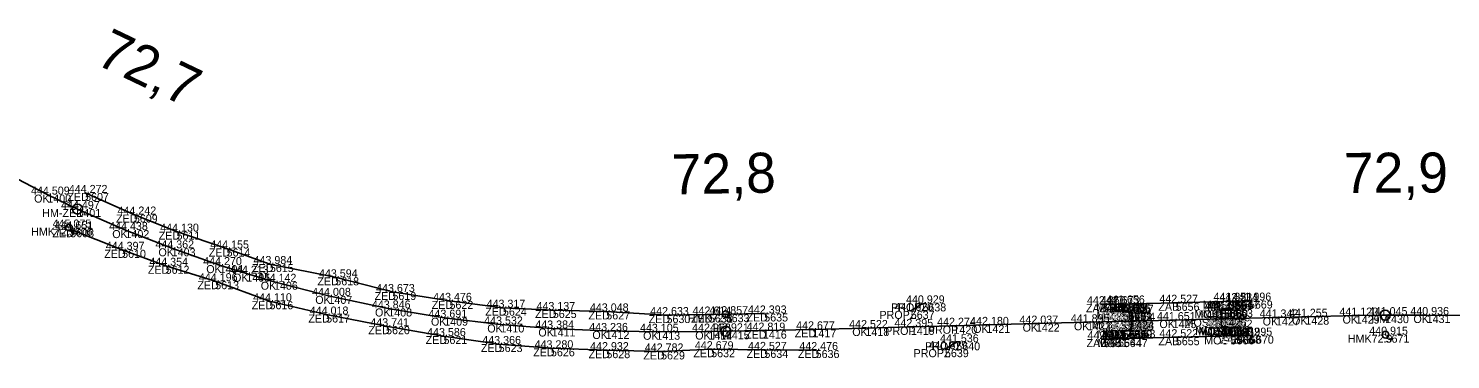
# Model space of a CAD drawing. Extents: x -621782 to -610392, y -1141853 to -1122321.
# Drawn here: x -620166.2 to -619952.9, y -1128869.1 to -1128819.5 of the extents above; entities that cross this region are included whole.
import ezdxf

# ---------------------------------------------------------------- set-up
doc = ezdxf.new("R2010")
doc.units = 0
for name, color, linetype in [('Vrstva 1', 7, 'Continuous'), ('Vrstva 13', 7, 'Continuous'), ('Vrstva 17', 7, 'Continuous'), ('Vrstva 18', 7, 'Continuous'), ('Vrstva 19', 7, 'Continuous'), ('Vrstva 60', 7, 'Continuous'), ('Vrstva 61', 7, 'Continuous'), ('Vrstva 62', 7, 'Continuous'), ('Vrstva 7', 7, 'Continuous')]:
    doc.layers.add(name, color=color, linetype=linetype)

msp = doc.modelspace()

# ---------------------------------------------------------------- linework, layer by layer
at = {"layer": 'Vrstva 1'}
msp.add_lwpolyline([(-620170.13, -1128840.86), (-620163.39, -1128844.36), (-620158.88, -1128846.52), (-620151.67, -1128849.68), (-620144.73, -1128852.41), (-620137.56, -1128854.93), (-620133.54, -1128856.21), (-620129.39, -1128857.43), (-620121.22, -1128859.54), (-620112.25, -1128861.43), (-620103.86, -1128862.81), (-620095.42, -1128863.83), (-620087.75, -1128864.43), (-620079.66, -1128864.8), (-620072.05, -1128864.92), (-620064.23, -1128864.89), (-620061.62, -1128864.85), (-620056.06, -1128864.75), (-620048.63, -1128864.56), (-620040.68, -1128864.36), (-620033.87, -1128864.19), (-620027.48, -1128864.02), (-620022.53, -1128863.89), (-620015.12, -1128863.7), (-620007.43, -1128863.5), (-620000.99, -1128863.33), (-619994.61, -1128863.17), (-619987.09, -1128862.97), (-619979.11, -1128862.78), (-619974.7, -1128862.67), (-619967.14, -1128862.5), (-619962.74, -1128862.43), (-619956.51, -1128862.41), (-619950.41, -1128862.49)], dxfattribs=at)
at = {"layer": 'Vrstva 13'}
for points in [[(-620157.72, -1128844.11), (-620150.41, -1128847.35), (-620144.01, -1128849.91), (-620136.5, -1128852.44), (-620130.01, -1128854.77), (-620120.2, -1128856.76), (-620111.63, -1128858.96), (-620103.07, -1128860.29), (-620095.05, -1128861.31), (-620087.57, -1128861.66), (-620079.55, -1128861.87), (-620070.52, -1128862.42), (-620064.16, -1128862.34), (-620055.86, -1128862.18)], [(-620048.15, -1128867.66), (-620055.84, -1128867.64), (-620063.82, -1128867.54), (-620071.33, -1128867.87), (-620079.54, -1128867.68), (-620087.85, -1128867.4), (-620095.69, -1128866.76), (-620103.97, -1128865.56), (-620112.58, -1128864.09), (-620121.57, -1128862.34), (-620130.07, -1128860.35), (-620138.21, -1128857.34), (-620145.64, -1128855.03), (-620152.17, -1128852.64), (-620159.95, -1128849.55)]]:
    msp.add_lwpolyline(points, dxfattribs=at)
at = {"layer": 'Vrstva 17'}
for points in [[(-619983.17, -1128860.25), (-619985.15, -1128860.33), (-619994.15, -1128860.57), (-620002.94, -1128860.77), (-620005.01, -1128860.79)], [(-620004.92, -1128866.03), (-620002.79, -1128865.97), (-619994.13, -1128865.74), (-619984.91, -1128865.52), (-619983.01, -1128865.5)]]:
    msp.add_lwpolyline(points, dxfattribs=at)
at = {"layer": 'Vrstva 18'}
for points in [[(-620001.93, -1128866.02), (-620001.95, -1128864.72), (-620001.24, -1128864.71), (-620001.23, -1128864.64), (-620000.76, -1128864.62), (-620000.8, -1128862.07), (-620001.26, -1128862.08), (-620001.29, -1128861.9), (-620002.09, -1128861.93), (-620002.14, -1128860.68)], [(-619985.93, -1128865.62), (-619985.98, -1128864.31), (-619986.77, -1128864.33), (-619986.79, -1128864.17), (-619987.28, -1128864.2), (-619987.39, -1128861.71), (-619986.9, -1128861.67), (-619986.9, -1128861.55), (-619986.14, -1128861.54), (-619986.12, -1128860.27)]]:
    msp.add_lwpolyline(points, dxfattribs=at)
at = {"layer": 'Vrstva 19'}
for p, q in [((-620033.88, -1128861.79), (-620032.14, -1128860.67)), ((-620028.76, -1128867.53), (-620027.05, -1128866.5))]:
    msp.add_line(p, q, dxfattribs=at)
at = {"layer": 'Vrstva 60'}
for p, q in [((-620163.39, -1128844.36), (-620163.39, -1128844.36)), ((-620157.72, -1128844.11), (-620157.72, -1128844.11)), ((-620158.88, -1128846.52), (-620158.88, -1128846.52)), ((-620150.41, -1128847.35), (-620150.41, -1128847.35)), ((-620160.15, -1128849.3), (-620160.15, -1128849.3)), ((-620159.95, -1128849.55), (-620159.95, -1128849.55)), ((-620151.67, -1128849.68), (-620151.67, -1128849.68)), ((-620144.01, -1128849.91), (-620144.01, -1128849.91)), ((-620152.17, -1128852.64), (-620152.17, -1128852.64)), ((-620144.73, -1128852.41), (-620144.73, -1128852.41)), ((-620136.5, -1128852.44), (-620136.5, -1128852.44)), ((-620145.64, -1128855.03), (-620145.64, -1128855.03)), ((-620137.56, -1128854.93), (-620137.56, -1128854.93)), ((-620130.01, -1128854.77), (-620130.01, -1128854.77)), ((-620138.21, -1128857.34), (-620138.21, -1128857.34)), ((-620133.54, -1128856.21), (-620133.54, -1128856.21)), ((-620129.39, -1128857.43), (-620129.39, -1128857.43)), ((-620120.2, -1128856.76), (-620120.2, -1128856.76)), ((-620121.22, -1128859.54), (-620121.22, -1128859.54)), ((-620111.63, -1128858.96), (-620111.63, -1128858.96)), ((-620130.07, -1128860.35), (-620130.07, -1128860.35)), ((-620112.25, -1128861.43), (-620112.25, -1128861.43)), ((-620103.07, -1128860.29), (-620103.07, -1128860.29)), ((-620095.05, -1128861.31), (-620095.05, -1128861.31)), ((-620087.57, -1128861.66), (-620087.57, -1128861.66)), ((-620079.55, -1128861.87), (-620079.55, -1128861.87)), ((-620061.64, -1128862.29), (-620061.64, -1128862.29)), ((-620055.86, -1128862.18), (-620055.86, -1128862.18)), ((-620033.88, -1128861.79), (-620033.88, -1128861.79)), ((-620032.14, -1128860.67), (-620032.14, -1128860.67)), ((-620005.01, -1128860.79), (-620005.01, -1128860.79)), ((-620002.94, -1128860.77), (-620002.94, -1128860.77)), ((-620002.14, -1128860.68), (-620002.14, -1128860.68)), ((-620002.09, -1128861.93), (-620002.09, -1128861.93)), ((-620001.29, -1128861.9), (-620001.29, -1128861.9)), ((-620001.26, -1128862.08), (-620001.26, -1128862.08)), ((-620000.8, -1128862.07), (-620000.8, -1128862.07)), ((-619994.15, -1128860.57), (-619994.15, -1128860.57)), ((-619987.39, -1128861.71), (-619987.39, -1128861.71)), ((-619986.9, -1128861.55), (-619986.9, -1128861.55)), ((-619986.9, -1128861.67), (-619986.9, -1128861.67)), ((-619986.14, -1128861.54), (-619986.14, -1128861.54)), ((-619986.12, -1128860.27), (-619986.12, -1128860.27)), ((-619985.15, -1128860.33), (-619985.15, -1128860.33)), ((-619983.17, -1128860.25), (-619983.17, -1128860.25)), ((-620121.57, -1128862.34), (-620121.57, -1128862.34)), ((-620112.58, -1128864.09), (-620112.58, -1128864.09)), ((-620103.86, -1128862.81), (-620103.86, -1128862.81)), ((-620095.42, -1128863.83), (-620095.42, -1128863.83)), ((-620087.75, -1128864.43), (-620087.75, -1128864.43)), ((-620070.52, -1128862.42), (-620070.52, -1128862.42)), ((-620064.16, -1128862.34), (-620064.16, -1128862.34)), ((-620040.68, -1128864.36), (-620040.68, -1128864.36)), ((-620033.87, -1128864.19), (-620033.87, -1128864.19)), ((-620027.48, -1128864.02), (-620027.48, -1128864.02)), ((-620022.53, -1128863.89), (-620022.53, -1128863.89)), ((-620015.12, -1128863.7), (-620015.12, -1128863.7)), ((-620007.43, -1128863.5), (-620007.43, -1128863.5)), ((-620000.99, -1128863.33), (-620000.99, -1128863.33)), ((-619994.61, -1128863.17), (-619994.61, -1128863.17)), ((-619987.28, -1128864.2), (-619987.28, -1128864.2)), ((-619987.09, -1128862.97), (-619987.09, -1128862.97)), ((-619986.79, -1128864.17), (-619986.79, -1128864.17)), ((-619986.77, -1128864.33), (-619986.77, -1128864.33)), ((-619985.98, -1128864.31), (-619985.98, -1128864.31)), ((-619979.11, -1128862.78), (-619979.11, -1128862.78)), ((-619974.7, -1128862.67), (-619974.7, -1128862.67)), ((-619967.14, -1128862.5), (-619967.14, -1128862.5)), ((-619962.74, -1128862.43), (-619962.74, -1128862.43)), ((-619956.51, -1128862.41), (-619956.51, -1128862.41)), ((-620103.97, -1128865.56), (-620103.97, -1128865.56)), ((-620079.66, -1128864.8), (-620079.66, -1128864.8)), ((-620072.05, -1128864.92), (-620072.05, -1128864.92)), ((-620064.23, -1128864.89), (-620064.23, -1128864.89)), ((-620061.62, -1128864.85), (-620061.62, -1128864.85)), ((-620056.06, -1128864.75), (-620056.06, -1128864.75)), ((-620048.63, -1128864.56), (-620048.63, -1128864.56)), ((-620027.05, -1128866.5), (-620027.05, -1128866.5)), ((-620004.92, -1128866.03), (-620004.92, -1128866.03)), ((-620002.79, -1128865.97), (-620002.79, -1128865.97)), ((-620001.95, -1128864.72), (-620001.95, -1128864.72)), ((-620001.93, -1128866.02), (-620001.93, -1128866.02)), ((-620001.24, -1128864.71), (-620001.24, -1128864.71)), ((-620001.23, -1128864.64), (-620001.23, -1128864.64)), ((-620000.76, -1128864.62), (-620000.76, -1128864.62)), ((-619994.13, -1128865.74), (-619994.13, -1128865.74)), ((-619985.93, -1128865.62), (-619985.93, -1128865.62)), ((-619984.91, -1128865.52), (-619984.91, -1128865.52)), ((-619983.01, -1128865.5), (-619983.01, -1128865.5)), ((-619962.67, -1128865.36), (-619962.67, -1128865.36)), ((-620095.69, -1128866.76), (-620095.69, -1128866.76)), ((-620087.85, -1128867.4), (-620087.85, -1128867.4)), ((-620079.54, -1128867.68), (-620079.54, -1128867.68)), ((-620071.33, -1128867.87), (-620071.33, -1128867.87)), ((-620063.82, -1128867.54), (-620063.82, -1128867.54)), ((-620055.84, -1128867.64), (-620055.84, -1128867.64)), ((-620048.15, -1128867.66), (-620048.15, -1128867.66)), ((-620028.76, -1128867.53), (-620028.76, -1128867.53))]:
    msp.add_line(p, q, dxfattribs=at)
at = {"layer": 'Vrstva 7'}
for p, q in [((-620160.19, -1128849.28), (-620160.1, -1128849.32)), ((-620061.69, -1128862.29), (-620061.59, -1128862.29)), ((-619962.72, -1128865.36), (-619962.62, -1128865.36))]:
    msp.add_line(p, q, dxfattribs=at)
for centre, radius in [((-620158.88, -1128846.52), 0.75), ((-620160.15, -1128849.3), 0.5), ((-620061.64, -1128862.29), 0.5), ((-619962.74, -1128862.43), 0.75), ((-620061.62, -1128864.85), 0.75), ((-619962.67, -1128865.36), 0.5)]:
    msp.add_circle(centre, radius, dxfattribs=at)

# ---------------------------------------------------------------- texts
at = {"layer": 'Vrstva 60'}
for s, p in [('1400', (-620163.39, -1128845.56)), ('5607', (-620157.72, -1128845.31)), ('1401', (-620158.88, -1128847.72)), ('5609', (-620150.41, -1128848.55)), ('5606', (-620160.15, -1128850.5)), ('5608', (-620159.95, -1128850.75)), ('1402', (-620151.67, -1128850.88)), ('5611', (-620144.01, -1128851.11)), ('5610', (-620152.17, -1128853.84)), ('1403', (-620144.73, -1128853.61)), ('5614', (-620136.5, -1128853.64)), ('5612', (-620145.64, -1128856.23)), ('1404', (-620137.56, -1128856.13)), ('5615', (-620130.01, -1128855.97)), ('5613', (-620138.21, -1128858.54)), ('1405', (-620133.54, -1128857.41)), ('1406', (-620129.39, -1128858.62)), ('5618', (-620120.2, -1128857.96)), ('1407', (-620121.22, -1128860.74)), ('5619', (-620111.63, -1128860.16)), ('5616', (-620130.07, -1128861.55)), ('1408', (-620112.25, -1128862.63)), ('5622', (-620103.07, -1128861.49)), ('5624', (-620095.05, -1128862.51)), ('5625', (-620087.57, -1128862.86)), ('5627', (-620079.55, -1128863.07)), ('5633', (-620061.64, -1128863.49)), ('5635', (-620055.86, -1128863.38)), ('5637', (-620033.88, -1128862.99)), ('5638', (-620032.14, -1128861.87)), ('5642', (-620005.01, -1128861.99)), ('5643', (-620002.94, -1128861.97)), ('5645', (-620002.14, -1128861.88)), ('5646', (-620002.09, -1128863.12)), ('5651', (-620001.29, -1128863.1)), ('5652', (-620001.26, -1128863.28)), ('5654', (-620000.8, -1128863.27)), ('5656', (-619994.15, -1128861.78)), ('5657', (-619987.39, -1128862.91)), ('5659', (-619986.9, -1128862.87)), ('5660', (-619986.9, -1128862.75)), ('5663', (-619986.14, -1128862.74)), ('5664', (-619986.12, -1128861.47)), ('5667', (-619985.15, -1128861.53)), ('5669', (-619983.17, -1128861.45)), ('5617', (-620121.57, -1128863.54)), ('5620', (-620112.58, -1128865.29)), ('1409', (-620103.86, -1128864.01)), ('1410', (-620095.42, -1128865.03)), ('1411', (-620087.75, -1128865.63)), ('5630', (-620070.52, -1128863.62)), ('5631', (-620064.16, -1128863.54)), ('1418', (-620040.68, -1128865.56)), ('1419', (-620033.87, -1128865.39)), ('1420', (-620027.48, -1128865.22)), ('1421', (-620022.53, -1128865.09)), ('1422', (-620015.12, -1128864.9)), ('1423', (-620007.43, -1128864.7)), ('1424', (-620000.99, -1128864.53)), ('1425', (-619994.61, -1128864.37)), ('5658', (-619987.28, -1128865.4)), ('1426', (-619987.09, -1128864.17)), ('5661', (-619986.79, -1128865.37)), ('5662', (-619986.77, -1128865.53)), ('5665', (-619985.98, -1128865.52)), ('1427', (-619979.11, -1128863.98)), ('1428', (-619974.7, -1128863.86)), ('1429', (-619967.14, -1128863.7)), ('1430', (-619962.74, -1128863.63)), ('1431', (-619956.51, -1128863.61)), ('5621', (-620103.97, -1128866.76)), ('1412', (-620079.66, -1128866)), ('1413', (-620072.05, -1128866.12)), ('1414', (-620064.23, -1128866.09)), ('1415', (-620061.62, -1128866.05)), ('1416', (-620056.06, -1128865.95)), ('1417', (-620048.63, -1128865.76)), ('5640', (-620027.05, -1128867.7)), ('5641', (-620004.92, -1128867.23)), ('5644', (-620002.79, -1128867.17)), ('5648', (-620001.95, -1128865.92)), ('5647', (-620001.93, -1128867.22)), ('5649', (-620001.24, -1128865.91)), ('5650', (-620001.23, -1128865.84)), ('5653', (-620000.76, -1128865.82)), ('5655', (-619994.13, -1128866.94)), ('5666', (-619985.93, -1128866.82)), ('5668', (-619984.91, -1128866.72)), ('5670', (-619983.01, -1128866.7)), ('5671', (-619962.67, -1128866.56)), ('5623', (-620095.69, -1128867.96)), ('5626', (-620087.85, -1128868.6)), ('5628', (-620079.54, -1128868.88)), ('5629', (-620071.33, -1128869.07)), ('5632', (-620063.82, -1128868.74)), ('5634', (-620055.84, -1128868.84)), ('5636', (-620048.15, -1128868.86)), ('5639', (-620028.76, -1128868.73))]:
    msp.add_text(s, height=1.2, dxfattribs=at).set_placement(p)
at = {"layer": 'Vrstva 61'}
for s, p in [('444.272', (-620160.17, -1128844.11)), ('444.509', (-620165.84, -1128844.36)), ('444.497', (-620161.33, -1128846.52)), ('444.242', (-620152.86, -1128847.35)), ('445.075', (-620162.6, -1128849.3)), ('444.651', (-620162.31, -1128849.55)), ('444.438', (-620154.12, -1128849.68)), ('444.130', (-620146.46, -1128849.91)), ('444.397', (-620154.62, -1128852.64)), ('444.362', (-620147.18, -1128852.41)), ('444.155', (-620138.95, -1128852.44)), ('444.270', (-620140.01, -1128854.93)), ('443.984', (-620132.46, -1128854.77)), ('444.354', (-620148.09, -1128855.03)), ('444.213', (-620135.99, -1128856.21)), ('443.594', (-620122.65, -1128856.76)), ('444.196', (-620140.66, -1128857.34)), ('444.142', (-620131.84, -1128857.43)), ('443.673', (-620114.08, -1128858.96)), ('444.110', (-620132.52, -1128860.35)), ('444.008', (-620123.67, -1128859.54)), ('443.476', (-620105.52, -1128860.29)), ('443.317', (-620097.5, -1128861.31)), ('440.929', (-620034.6, -1128860.67)), ('442.360', (-620007.46, -1128860.79)), ('442.673', (-620005.39, -1128860.77)), ('441.656', (-620004.59, -1128860.68)), ('442.527', (-619996.6, -1128860.57)), ('441.351', (-619988.48, -1128860.27)), ('442.334', (-619987.6, -1128860.33)), ('441.996', (-619985.62, -1128860.25)), ('444.018', (-620124.03, -1128862.34)), ('443.846', (-620114.71, -1128861.43)), ('443.691', (-620106.22, -1128862.81)), ('443.137', (-620090.02, -1128861.66)), ('443.048', (-620082.01, -1128861.87)), ('442.633', (-620072.97, -1128862.42)), ('442.614', (-620066.61, -1128862.34)), ('442.857', (-620064.09, -1128862.29)), ('442.393', (-620058.31, -1128862.18)), ('441.620', (-620036.33, -1128861.79)), ('441.895', (-620009.88, -1128863.5)), ('441.660', (-620004.54, -1128861.93)), ('441.666', (-620003.74, -1128861.9)), ('441.665', (-620003.72, -1128862.08)), ('441.773', (-620003.44, -1128863.33)), ('441.687', (-620003.25, -1128862.07)), ('441.651', (-619996.96, -1128863.17)), ('441.429', (-619989.84, -1128861.71)), ('441.495', (-619989.55, -1128862.97)), ('441.385', (-619989.36, -1128861.67)), ('441.389', (-619989.35, -1128861.55)), ('441.363', (-619988.59, -1128861.54)), ('441.342', (-619981.56, -1128862.78)), ('441.255', (-619977.16, -1128862.67)), ('441.120', (-619969.59, -1128862.5)), ('441.045', (-619965.19, -1128862.43)), ('440.936', (-619958.96, -1128862.41)), ('443.741', (-620114.94, -1128864.09)), ('443.586', (-620106.43, -1128865.56)), ('443.532', (-620097.87, -1128863.83)), ('443.384', (-620090.2, -1128864.43)), ('443.236', (-620082.11, -1128864.8)), ('443.105', (-620074.5, -1128864.92)), ('442.968', (-620066.68, -1128864.89)), ('442.921', (-620063.98, -1128864.85)), ('442.819', (-620058.51, -1128864.75)), ('442.677', (-620051.08, -1128864.56)), ('442.522', (-620043.13, -1128864.36)), ('442.395', (-620036.33, -1128864.19)), ('442.274', (-620029.93, -1128864.02)), ('442.180', (-620024.98, -1128863.89)), ('442.037', (-620017.58, -1128863.7)), ('441.669', (-620004.41, -1128864.72)), ('441.677', (-620003.69, -1128864.71)), ('441.675', (-620003.69, -1128864.64)), ('441.693', (-620003.21, -1128864.62)), ('441.411', (-619989.63, -1128864.2)), ('441.397', (-619989.22, -1128864.33)), ('441.391', (-619989.14, -1128864.17)), ('441.402', (-619988.43, -1128864.31)), ('441.380', (-619988.38, -1128865.62)), ('442.322', (-619987.35, -1128865.52)), ('441.995', (-619985.47, -1128865.5)), ('440.915', (-619965.12, -1128865.36)), ('443.366', (-620098.15, -1128866.76)), ('443.280', (-620090.3, -1128867.4)), ('442.932', (-620081.98, -1128867.68)), ('442.679', (-620066.27, -1128867.54)), ('442.527', (-620058.29, -1128867.64)), ('442.476', (-620050.6, -1128867.66)), ('440.879', (-620031.21, -1128867.53)), ('441.536', (-620029.5, -1128866.5)), ('442.389', (-620007.37, -1128866.03)), ('442.675', (-620005.25, -1128865.97)), ('441.653', (-620004.38, -1128866.02)), ('442.522', (-619996.58, -1128865.74)), ('442.782', (-620073.78, -1128867.87))]:
    msp.add_text(s, height=1.2, dxfattribs=at).set_placement(p)
at = {"layer": 'Vrstva 62'}
for s, p in [('OK', (-620165.37, -1128845.56)), ('ZED', (-620160.39, -1128845.31)), ('HM-ZED', (-620164.15, -1128847.72)), ('ZED', (-620153.09, -1128848.55)), ('HMK72.7', (-620165.81, -1128850.5)), ('ZED', (-620162.63, -1128850.75)), ('OK', (-620153.65, -1128850.88)), ('ZED', (-620146.68, -1128851.11)), ('ZED', (-620154.85, -1128853.84)), ('OK', (-620146.72, -1128853.61)), ('ZED', (-620139.17, -1128853.64)), ('ZED', (-620148.31, -1128856.23)), ('OK', (-620139.55, -1128856.13)), ('ZED', (-620132.68, -1128855.97)), ('ZED', (-620140.88, -1128858.54)), ('OK', (-620135.53, -1128857.41)), ('OK', (-620131.38, -1128858.62)), ('ZED', (-620122.88, -1128857.96)), ('OK', (-620123.2, -1128860.74)), ('ZED', (-620114.31, -1128860.16)), ('ZED', (-620132.74, -1128861.55)), ('OK', (-620114.24, -1128862.63)), ('ZED', (-620105.74, -1128861.49)), ('ZED', (-620097.72, -1128862.51)), ('ZED', (-620090.24, -1128862.86)), ('ZED', (-620082.23, -1128863.07)), ('HMK72.8', (-620067.31, -1128863.49)), ('ZED', (-620058.53, -1128863.38)), ('PROPZ', (-620038.58, -1128862.99)), ('PROPZ', (-620036.84, -1128861.87)), ('ZAB', (-620007.61, -1128861.99)), ('MOST', (-620006.08, -1128861.88)), ('MOST', (-620006.03, -1128863.12)), ('ZAB', (-620005.54, -1128861.97)), ('MOST', (-620005.24, -1128863.1)), ('MOST', (-620005.21, -1128863.28)), ('MOST', (-620004.74, -1128863.27)), ('ZAB', (-619996.75, -1128861.78)), ('MOST', (-619991.33, -1128862.91)), ('MOST', (-619990.85, -1128862.87)), ('MOST', (-619990.84, -1128862.75)), ('MOST', (-619990.08, -1128862.74)), ('MOST', (-619990.07, -1128861.47)), ('ZAB', (-619987.75, -1128861.53)), ('ZAB', (-619985.77, -1128861.45)), ('ZED', (-620124.24, -1128863.54)), ('ZED', (-620115.25, -1128865.29)), ('OK', (-620105.85, -1128864.01)), ('OK', (-620097.4, -1128865.03)), ('OK', (-620089.74, -1128865.63)), ('ZED', (-620073.19, -1128863.62)), ('ZED', (-620066.83, -1128863.54)), ('OK', (-620042.66, -1128865.56)), ('PROP', (-620037.71, -1128865.39)), ('PROP', (-620031.32, -1128865.22)), ('OK', (-620024.52, -1128865.09)), ('OK', (-620017.11, -1128864.9)), ('OK', (-620009.41, -1128864.7)), ('MOSTBS', (-620006.72, -1128864.53)), ('OK', (-619996.59, -1128864.37)), ('MOSTBS', (-619992.82, -1128864.17)), ('MOST', (-619991.22, -1128865.4)), ('MOST', (-619990.73, -1128865.37)), ('MOST', (-619990.72, -1128865.53)), ('MOST', (-619989.93, -1128865.52)), ('OK', (-619981.1, -1128863.98)), ('OK', (-619976.69, -1128863.86)), ('OK', (-619969.12, -1128863.7)), ('HM', (-619964.77, -1128863.63)), ('OK', (-619958.49, -1128863.61)), ('ZED', (-620106.65, -1128866.76)), ('OK', (-620081.64, -1128866)), ('OK', (-620074.03, -1128866.12)), ('OK', (-620066.21, -1128866.09)), ('HM', (-620063.65, -1128866.05)), ('ZED', (-620058.73, -1128865.95)), ('ZED', (-620051.3, -1128865.76)), ('PROPZ', (-620031.75, -1128867.7)), ('ZAB', (-620007.52, -1128867.23)), ('MOST', (-620005.9, -1128865.92)), ('MOST', (-620005.87, -1128867.22)), ('ZAB', (-620005.39, -1128867.17)), ('MOST', (-620005.18, -1128865.84)), ('MOST', (-620005.19, -1128865.91)), ('MOST', (-620004.71, -1128865.82)), ('ZAB', (-619996.73, -1128866.94)), ('MOST', (-619989.87, -1128866.82)), ('ZAB', (-619987.51, -1128866.72)), ('ZAB', (-619985.61, -1128866.7)), ('HMK72.9', (-619968.33, -1128866.56)), ('ZED', (-620098.37, -1128867.96)), ('ZED', (-620090.52, -1128868.6)), ('ZED', (-620082.21, -1128868.88)), ('ZED', (-620074, -1128869.07)), ('ZED', (-620066.49, -1128868.74)), ('ZED', (-620058.52, -1128868.84)), ('ZED', (-620050.82, -1128868.86)), ('PROPZ', (-620033.46, -1128868.73))]:
    msp.add_text(s, height=1.2, dxfattribs=at).set_placement(p)
at = {"layer": 'Vrstva 7'}
for s, rotation, p in [('72,7', 334.414, (-620156.37, -1128824.69)), ('72,8', 1.1027, (-620069.69, -1128844.34)), ('72,9', 0.23, (-619968.92, -1128844.11))]:
    msp.add_text(s, height=6, rotation=rotation, dxfattribs=at).set_placement(p)

doc.saveas('drawing.dxf')
